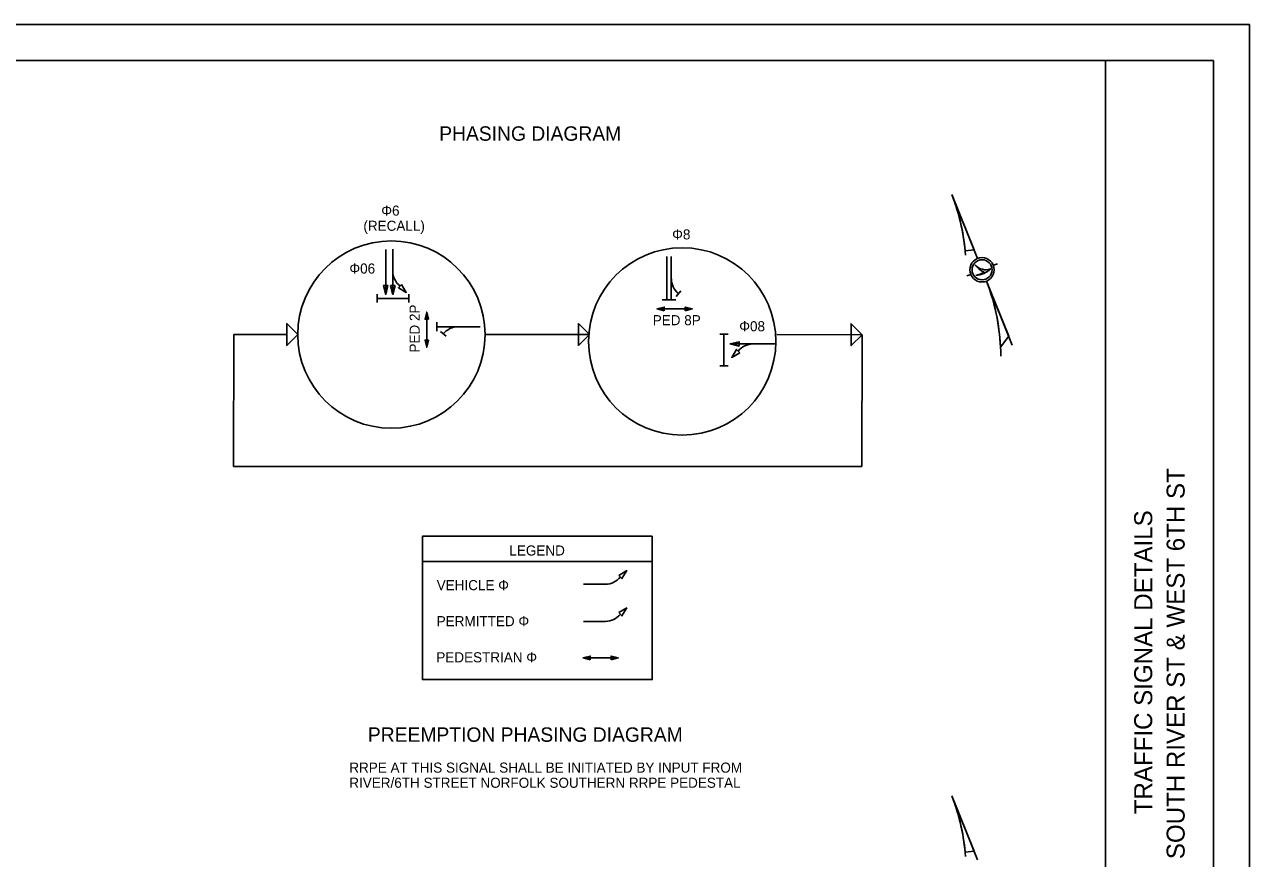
# Model space of a CAD drawing. Extents: x 0 to 680, y 0 to 440.
# Drawn here: x 340 to 680, y 208.6 to 440 of the extents above; entities that cross this region are included whole.
import ezdxf

# ---------------------------------------------------------------- set-up
doc = ezdxf.new("R2010")
doc.units = 0
for name, color, linetype in [('SG_P_Text', 7, 'Continuous'), ('SH_Border', 7, 'Continuous'), ('SH_Cut_Line', 7, 'Continuous'), ('SH_Data', 7, 'Continuous'), ('SH_Text', 7, 'Continuous')]:
    doc.layers.add(name, color=color, linetype=linetype)

msp = doc.modelspace()

# ---------------------------------------------------------------- linework, layer by layer
at = {"layer": 'SG_P_Text'}
for p, q in [((440.25, 365.09), (440.25, 377.55)), ((442.23, 377.65), (442.23, 371.54)), ((442.25, 365.09), (442.25, 377.55)), ((518.26, 375.58), (518.26, 363.56)), ((519.52, 375.58), (519.52, 369.47)), ((519.52, 375.58), (519.52, 363.56)), ((437.89, 365.15), (437.89, 362.87)), ((437.89, 364.01), (446.67, 364.01)), ((446.67, 365.15), (446.67, 362.87)), ((520.86, 364.54), (522.14, 366.13)), ((515.59, 361.07), (525.35, 361.07)), ((519.52, 363.56), (516.99, 363.56)), ((520.79, 363.56), (518.26, 363.56)), ((451.66, 350.43), (451.66, 360.18)), ((454.44, 354.86), (454.44, 357.39)), ((398, 317.37), (398.06, 353.96)), ((398.06, 353.96), (412.8, 353.96)), ((466.45, 356.13), (454.44, 356.13)), ((455.42, 354.79), (457.01, 353.5)), ((466.45, 356.13), (460.34, 356.13)), ((496.82, 353.96), (467.82, 353.96)), ((535.28, 354.07), (533, 354.07)), ((534.14, 345.29), (534.14, 354.07)), ((572.45, 353.93), (548.8, 353.96)), ((572.39, 317.37), (572.45, 353.93)), ((535.84, 351.35), (548.3, 351.35)), ((548.3, 351.35), (542.19, 351.35)), ((535.28, 345.29), (533, 345.29)), ((572.39, 317.37), (398, 317.37)), ((450.42, 290.97), (514.23, 290.97)), ((495.14, 284.7), (501.25, 284.7)), ((495.14, 274.37), (501.25, 274.37)), ((495.04, 264.23), (504.79, 264.23))]:
    msp.add_line(p, q, dxfattribs=at)
for points in [[(440.87, 367.59), (440.25, 365.09), (439.62, 367.59)], [(442.87, 367.59), (442.25, 365.09), (441.62, 367.59)], [(444.65, 367.85), (445.97, 365.64), (443.76, 366.97)], [(517.57, 360.58), (515.59, 361.07), (517.57, 361.57)], [(523.37, 360.58), (525.35, 361.07), (523.37, 361.57)], [(452.15, 358.2), (451.66, 360.18), (451.16, 358.2)], [(415.83, 353.96), (412.8, 356.99), (412.8, 350.93)], [(496.82, 353.96), (493.79, 356.99), (493.79, 350.93)], [(572.45, 353.93), (569.42, 356.96), (569.42, 350.9)], [(452.15, 352.41), (451.66, 350.43), (451.16, 352.41)], [(538.34, 350.73), (535.84, 351.35), (538.34, 351.98)], [(538.5, 348.93), (536.29, 347.61), (537.62, 349.82)], [(514.23, 297.97), (450.46, 297.97), (450.46, 258.22), (514.23, 258.22)], [(504.94, 287.13), (507.15, 288.45), (505.82, 286.24)], [(504.94, 276.79), (507.15, 278.11), (505.82, 275.9)], [(497.02, 263.73), (495.04, 264.23), (497.02, 264.72)], [(502.81, 263.73), (504.79, 264.23), (502.81, 264.72)]]:
    msp.add_lwpolyline(points, close=True, dxfattribs=at)
for centre in [(441.83, 353.96), (522.54, 352.05)]:
    msp.add_circle(centre, 25.99, dxfattribs=at)
for centre, start, end in [((447.53, 371.54), 180, 231.2007), ((524.83, 369.47), 180, 231.2007), ((460.35, 350.82), 90.0129, 141.2136), ((542.19, 346.05), 90, 141.2007), ((501.25, 290), 270.0129, 321.2136), ((501.25, 279.67), 270, 321.2007)]:
    msp.add_arc(centre, 5.3, start, end, dxfattribs=at)
at = {"layer": 'SH_Border'}
msp.add_line((640, 10), (640, 430), dxfattribs=at)
msp.add_lwpolyline([(30, 430), (670, 430), (670, 10), (30, 10)], close=True, dxfattribs=at)
at = {"layer": 'SH_Cut_Line'}
msp.add_lwpolyline([(0, 0), (680, 0), (680, 440), (0, 440)], close=True, dxfattribs=at)
at = {"layer": 'SH_Data'}
for p, q in [((604.52, 375.06), (597.41, 392.82)), ((601.1, 377.17), (603.56, 377.45)), ((601.52, 370.23), (602.64, 370.67)), ((608.91, 373.18), (610.02, 373.63)), ((614.13, 351.04), (607.03, 368.79)), ((613.16, 353.48), (610.89, 350.49)), ((604.52, 208.21), (597.41, 225.96)), ((601.1, 210.32), (603.56, 210.6))]:
    msp.add_line(p, q, dxfattribs=at)
for points in [[(601.08, 377.17), (601.1, 377.17), (603.56, 377.45), (597.41, 392.82)], [(610.89, 350.49), (613.16, 353.48), (607.03, 368.79)], [(601.08, 210.32), (601.1, 210.32), (603.56, 210.6), (597.41, 225.96)]]:
    msp.add_lwpolyline(points, dxfattribs=at)
for radius in [3.38, 2.78]:
    msp.add_circle((605.77, 371.93), radius, dxfattribs=at)
for centre, radius, start, end in [((542.2, 371.62), 59.14, 4.2256, 21.005), ((542.2, 371.62), 59.14, 5.3857, 21.005), ((606.78, 375.77), 3.82, 220.9677, 291.1812), ((608.31, 376.32), 5.38, 214.6659, 249.1244), ((603.51, 377.14), 6.79, 274.2977, 313.2963), ((602.15, 378.74), 8.57, 282.538, 299.6837), ((551.82, 347.6), 59.14, 0.3157, 21.005), ((551.82, 347.6), 59.14, 2.8039, 21.005), ((542.2, 204.76), 59.14, 4.2256, 21.005), ((542.2, 204.76), 59.14, 5.3857, 21.005)]:
    msp.add_arc(centre, radius, start, end, dxfattribs=at)

# ---------------------------------------------------------------- texts
at = {"layer": 'SG_P_Text'}
for s, p in [('Φ6', (439.03, 386.95)), ('(RECALL)', (434.06, 382.75)), (' Φ8', (518.72, 380.36)), ('Φ06', (430.17, 370.89)), ('Φ08', (538.38, 354.86)), ('LEGEND', (474.58, 292.64)), ('VEHICLE Φ', (454.41, 283.03)), ('PERMITTED Φ', (454.41, 273.03)), ('PEDESTRIAN Φ', (454.31, 263))]:
    msp.add_text(s, height=2.8, dxfattribs=at).set_placement(p)
for s, rotation, p in [('PED 2P', 90, (449.69, 348.97)), ('PED 8P', 360, (514.37, 356.55))]:
    msp.add_text(s, height=2.8, rotation=rotation, dxfattribs=at).set_placement(p)
at = {"layer": 'SH_Data'}
for s, p in [('SOUTH RIVER ST & WEST 6TH ST', (662, 208.39)), ('TRAFFIC SIGNAL DETAILS', (653, 220.85))]:
    msp.add_text(s, height=5, rotation=90, dxfattribs=at).set_placement(p)
at = {"layer": 'SH_Text'}
for s, height, p in [('PHASING DIAGRAM', 4, (455.1, 407.74)), ('PREEMPTION PHASING DIAGRAM', 4, (435.31, 240.95)), ('RRPE AT THIS SIGNAL SHALL BE INITIATED BY INPUT FROM', 2.8, (430.15, 232.39)), ('RIVER/6TH STREET NORFOLK SOUTHERN RRPE PEDESTAL', 2.8, (430.15, 228.19))]:
    msp.add_text(s, height=height, dxfattribs=at).set_placement(p)

doc.saveas('drawing.dxf')
